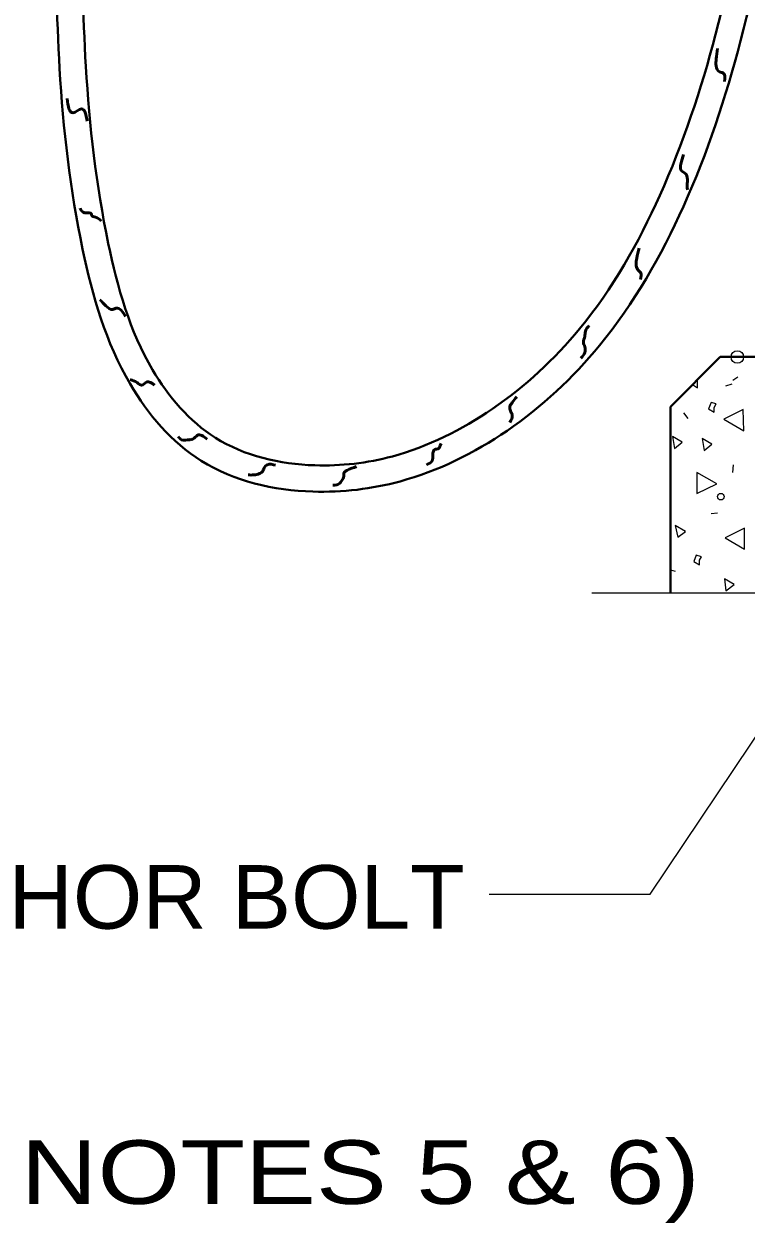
# Model space of a CAD drawing. Extents: x 312583 to 312854, y 144419 to 144597.
# Drawn here: x 312743.93 to 312752.56, y 144432.92 to 144447.26 of the extents above; entities that cross this region are included whole.
import ezdxf

# ---------------------------------------------------------------- set-up
doc = ezdxf.new("R2010")
doc.units = 0
doc.header["$LTSCALE"] = 0.3
doc.header["$PDMODE"] = 32
doc.header["$PDSIZE"] = 0.15
doc.layers.add('1', color=7, linetype='Continuous', lineweight=13)
doc.layers.add('2', color=7, linetype='Continuous', lineweight=13)

msp = doc.modelspace()

# ---------------------------------------------------------------- linework, layer by layer
at = {"layer": '1', "lineweight": 40}
for p, q in [((312752.253, 144443.2771), (312751.6627, 144442.6791)), ((312752.253, 144443.2771), (312779.577, 144443.2771)), ((312751.6627, 144440.4558), (312751.6627, 144442.6791))]:
    msp.add_line(p, q, dxfattribs=at)
at = {"layer": '1'}
msp.add_line((312750.7197, 144440.4558), (312759.7664, 144440.4558), dxfattribs=at)
msp.add_lwpolyline([(312749.493, 144436.8524), (312751.4174, 144436.8524), (312754.6374, 144441.6518)], dxfattribs=at)
at = {"layer": '1', "lineweight": 40}
for points in [[(312744.5787, 144450.6524), (312744.617, 144448.6208), (312744.6707, 144446.7501), (312744.939, 144444.6341), (312745.468, 144443.1238), (312746.2194, 144442.3111), (312747.4077, 144441.9814), (312748.3354, 144442.0888), (312749.5314, 144442.6561), (312750.574, 144443.6144), (312751.5324, 144445.2091), (312752.1994, 144447.1334), (312752.6364, 144449.3951), (312752.828, 144451.2811), (312753.5564, 144456.6631), (312753.9474, 144458.2271), (312754.346, 144459.3771), (312754.8137, 144460.3431), (312755.588, 144461.4241), (312756.7457, 144462.3211), (312758.072, 144462.8194), (312760.0577, 144463.5861), (312761.844, 144464.2454), (312763.431, 144464.8358)], [(312744.2644, 144450.6448), (312744.3027, 144448.6131), (312744.3564, 144446.7271), (312744.6324, 144444.5651), (312745.1997, 144442.9551), (312746.0507, 144442.0351), (312747.3847, 144441.6671), (312748.4274, 144441.7898), (312749.7077, 144442.3954), (312750.8117, 144443.4151), (312751.816, 144445.0788), (312752.4984, 144447.0568), (312752.943, 144449.3491), (312753.1347, 144451.2428), (312753.863, 144456.6018), (312754.2464, 144458.1428), (312754.6374, 144459.2621), (312755.082, 144460.1821), (312755.818, 144461.2018), (312756.899, 144462.0451), (312758.1794, 144462.5281), (312760.1727, 144463.2948), (312761.9514, 144463.9541), (312763.5384, 144464.5444)]]:
    msp.add_spline(points, degree=3, dxfattribs=at)
at = {"layer": '1', "lineweight": 53}
for points in [[(312752.2224, 144446.9648), (312752.207, 144446.8421), (312752.207, 144446.7578), (312752.2454, 144446.6888), (312752.2914, 144446.6734), (312752.3067, 144446.5738)], [(312744.686, 144446.0984), (312744.617, 144446.2441), (312744.5174, 144446.1981), (312744.4484, 144446.3668)], [(312751.816, 144445.6998), (312751.7854, 144445.5848), (312751.7854, 144445.5158), (312751.8467, 144445.4621), (312751.862, 144445.3778), (312751.862, 144445.2781)], [(312744.8547, 144444.9024), (312744.7857, 144444.9484), (312744.7397, 144444.9714), (312744.7397, 144444.9868), (312744.6554, 144445.0021), (312744.6017, 144445.0558)], [(312751.287, 144444.5804), (312751.2564, 144444.4578), (312751.2487, 144444.3888), (312751.2717, 144444.3198), (312751.3024, 144444.2891), (312751.3024, 144444.2048)], [(312745.146, 144443.7601), (312745.031, 144443.8598), (312744.9927, 144443.8444), (312744.9084, 144443.8904), (312744.8394, 144443.9594)], [(312750.689, 144443.6528), (312750.643, 144443.5838), (312750.6354, 144443.5224), (312750.62, 144443.4534), (312750.6354, 144443.3998), (312750.6354, 144443.3308), (312750.5894, 144443.2618)], [(312745.491, 144442.9398), (312745.399, 144442.9781), (312745.3377, 144442.9398), (312745.284, 144442.9704), (312745.1997, 144443.0088)], [(312749.8227, 144442.8018), (312749.769, 144442.7328), (312749.7384, 144442.6714), (312749.7537, 144442.6178), (312749.769, 144442.5794), (312749.7384, 144442.4951)], [(312746.1197, 144442.2958), (312746.0047, 144442.3418), (312745.951, 144442.2958), (312745.9127, 144442.2881), (312745.813, 144442.2881), (312745.7747, 144442.3264)], [(312748.918, 144442.2421), (312748.8644, 144442.1731), (312748.849, 144442.1731), (312748.8184, 144442.1041), (312748.8107, 144442.0351), (312748.7417, 144441.9891)], [(312746.94, 144441.9814), (312746.8404, 144441.9891), (312746.802, 144441.9508), (312746.7867, 144441.9124), (312746.7484, 144441.8818), (312746.6794, 144441.8664), (312746.6104, 144441.8664)], [(312747.906, 144441.9661), (312747.791, 144441.9201), (312747.7604, 144441.8971), (312747.7527, 144441.8358), (312747.7374, 144441.8128), (312747.7067, 144441.7668), (312747.6224, 144441.7438)]]:
    msp.add_spline(points, degree=3, dxfattribs=at)
at = {"layer": '2'}
for p, q in [((312751.9234, 144442.9474), (312751.9847, 144442.9091)), ((312751.9847, 144442.9091), (312751.9847, 144443.0088)), ((312752.322, 144442.9321), (312752.3987, 144442.9551)), ((312752.4064, 144443.0011), (312752.4677, 144443.0394)), ((312751.816, 144442.6101), (312751.8697, 144442.5411)), ((312752.4064, 144441.8971), (312752.414, 144441.9891)), ((312752.1457, 144441.4064), (312752.2224, 144441.4141)), ((312751.6627, 144440.7318), (312751.7164, 144440.7164))]:
    msp.add_line(p, q, dxfattribs=at)
for points in [[(312752.184, 144442.6714), (312752.207, 144442.7174), (312752.1457, 144442.7328), (312752.115, 144442.6561), (312752.184, 144442.6178)], [(312752.5367, 144442.3954), (312752.529, 144442.6484), (312752.299, 144442.5334)], [(312751.7087, 144442.1808), (312751.8007, 144442.2574), (312751.6857, 144442.3264)], [(312752.0614, 144442.1578), (312752.1534, 144442.2344), (312752.0384, 144442.3034)], [(312751.977, 144441.8971), (312751.977, 144441.6441), (312752.2147, 144441.7591)], [(312751.747, 144441.1228), (312751.839, 144441.1918), (312751.7164, 144441.2608)], [(312752.5444, 144440.9771), (312752.5444, 144441.2301), (312752.3144, 144441.1151)], [(312752.0077, 144440.8468), (312752.0307, 144440.8851), (312751.9694, 144440.9081), (312751.9387, 144440.8314), (312752.0077, 144440.7931)], [(312752.322, 144440.4788), (312752.4217, 144440.5554), (312752.3067, 144440.6244)]]:
    msp.add_lwpolyline(points, close=True, dxfattribs=at)
msp.add_circle((312752.2633, 144441.6066), 0.0392, dxfattribs=at)
msp.add_point((312752.46, 144443.2771), dxfattribs=at)

# ---------------------------------------------------------------- texts
at = {"layer": '1'}
for s, width, p in [('ANCHOR BOLT', 1.05, (312741.4917, 144436.4394)), ('(SEE NOTES 5 & 6)', 1.25, (312740.5744, 144433.1477))]:
    msp.add_text(s, height=0.76, dxfattribs=dict(at, width=width)).set_placement(p)

doc.saveas('drawing.dxf')
